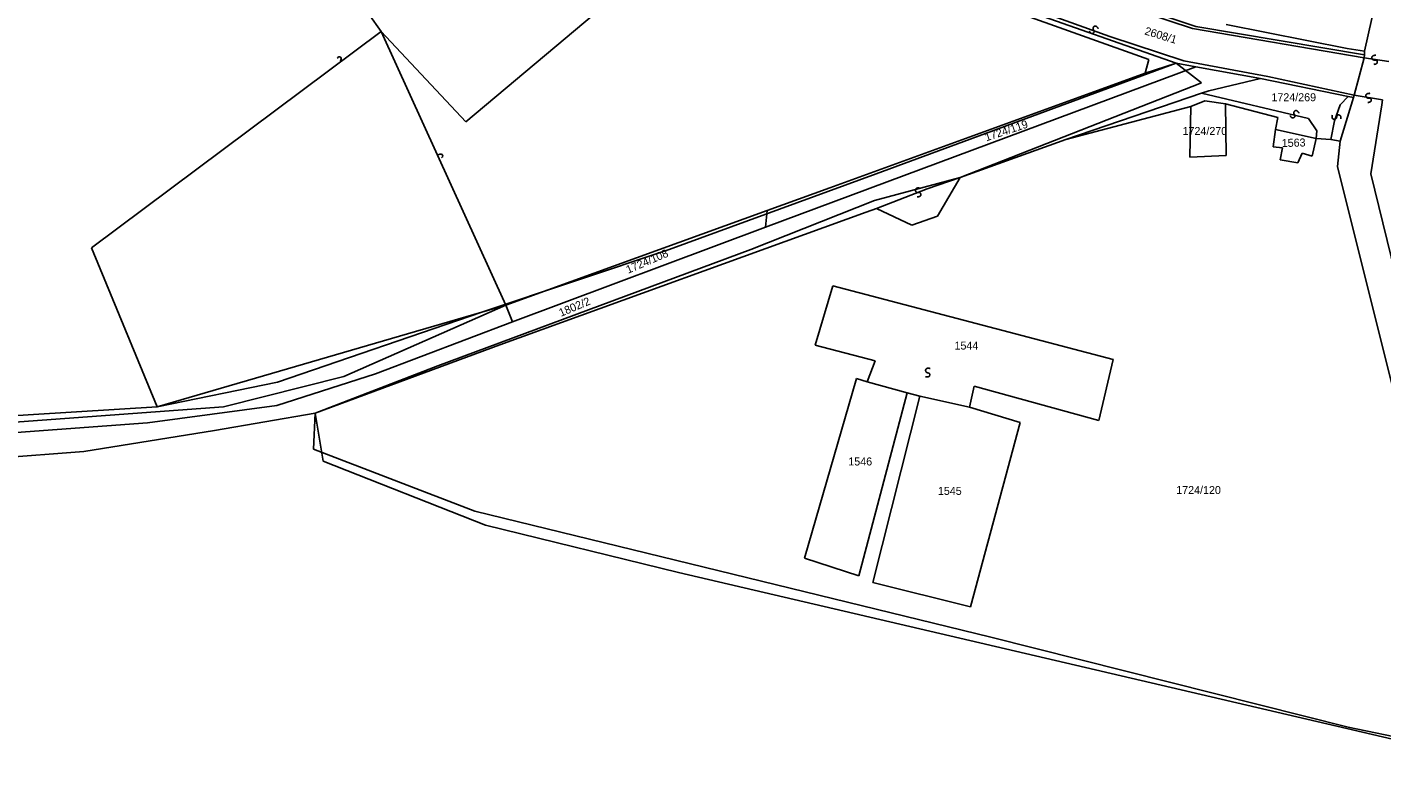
# Model space of a CAD drawing. Extents: x -581999 to -572728, y -1219553 to -1212032.
# Drawn here: x -578955.2 to -578616.8, y -1215563.4 to -1215379.4 of the extents above; entities that cross this region are included whole.
import ezdxf

# ---------------------------------------------------------------- set-up
doc = ezdxf.new("R2010")
doc.units = 0
for name, color, linetype in [('Vrstva 1', 7, 'Continuous'), ('Vrstva 2', 7, 'Continuous'), ('Vrstva 4', 7, 'Continuous'), ('Vrstva 6', 7, 'Continuous'), ('Vrstva 63', 7, 'Continuous')]:
    doc.layers.add(name, color=color, linetype=linetype)

msp = doc.modelspace()

# ---------------------------------------------------------------- linework, layer by layer
at = {"layer": 'Vrstva 1'}
for p, q in [((-578760.509, -1215331.523), (-578845.631, -1215403.127)), ((-578866.81, -1215380.502), (-578873.87, -1215370.57)), ((-578709.273, -1215375.274), (-578674.955, -1215387.516)), ((-578707.581, -1215374.594), (-578668.188, -1215388.422)), ((-578655.655, -1215378.755), (-578625.458, -1215384.809)), ((-578939.172, -1215434.581), (-578866.81, -1215380.502)), ((-578866.81, -1215380.502), (-578835.63, -1215448.928)), ((-578845.631, -1215403.127), (-578866.81, -1215380.502)), ((-578625.458, -1215384.809), (-578621.144, -1215385.458)), ((-578674.955, -1215387.516), (-578675.921, -1215390.916)), ((-578668.188, -1215388.422), (-578663.25, -1215389.334)), ((-578623.694, -1215396.422), (-578621.211, -1215387.123)), ((-578770.802, -1215429.419), (-578663.25, -1215389.334)), ((-578663.25, -1215389.334), (-578647.054, -1215392.279)), ((-578659.977, -1215395.359), (-578647.054, -1215392.279)), ((-578647.054, -1215392.279), (-578625.188, -1215396.746)), ((-578661.834, -1215395.951), (-578659.977, -1215395.359)), ((-578695.692, -1215407.535), (-578661.834, -1215395.951)), ((-578695.692, -1215407.535), (-578664.512, -1215399.258)), ((-578664.714, -1215411.951), (-578664.512, -1215399.258)), ((-578664.512, -1215399.258), (-578660.982, -1215397.879)), ((-578660.982, -1215397.879), (-578655.834, -1215398.568)), ((-578655.834, -1215398.568), (-578642.745, -1215402.017)), ((-578655.834, -1215398.568), (-578655.655, -1215411.519)), ((-578627.154, -1215407.949), (-578623.872, -1215397.051)), ((-578625.188, -1215396.746), (-578623.872, -1215397.051)), ((-578623.872, -1215397.051), (-578623.694, -1215396.422)), ((-578642.745, -1215402.017), (-578643.333, -1215405.052)), ((-578643.333, -1215405.052), (-578643.921, -1215409.329)), ((-578633.185, -1215407.26), (-578643.333, -1215405.052)), ((-578722.166, -1215417.055), (-578695.692, -1215407.535)), ((-578643.921, -1215409.329), (-578641.568, -1215409.605)), ((-578634.214, -1215411.674), (-578633.185, -1215407.26)), ((-578633.185, -1215407.26), (-578629.508, -1215407.535)), ((-578629.508, -1215407.535), (-578627.154, -1215407.949)), ((-578627.154, -1215407.949), (-578627.89, -1215414.295)), ((-578655.655, -1215411.519), (-578664.714, -1215411.951)), ((-578641.568, -1215409.605), (-578642.156, -1215412.64)), ((-578642.156, -1215412.64), (-578637.744, -1215413.33)), ((-578637.744, -1215413.33), (-578636.714, -1215410.984)), ((-578636.714, -1215410.984), (-578634.214, -1215411.674)), ((-578627.89, -1215414.295), (-578613.918, -1215470.029)), ((-578722.166, -1215417.055), (-578727.755, -1215426.711)), ((-578837.154, -1215458.836), (-578745.601, -1215425.733)), ((-578770.342, -1215425.262), (-578770.802, -1215429.419)), ((-578745.601, -1215425.733), (-578743.051, -1215424.78)), ((-578734.226, -1215428.919), (-578743.051, -1215424.78)), ((-578833.94, -1215453.161), (-578770.802, -1215429.419)), ((-578727.755, -1215426.711), (-578734.226, -1215428.919)), ((-578922.744, -1215474.383), (-578939.172, -1215434.581)), ((-578758.347, -1215458.993), (-578753.934, -1215444.094)), ((-578753.934, -1215444.094), (-578683.926, -1215462.579)), ((-578835.63, -1215448.928), (-578922.744, -1215474.383)), ((-578876.103, -1215466.802), (-578835.63, -1215448.928)), ((-578835.63, -1215448.928), (-578833.94, -1215453.161)), ((-578868.184, -1215466.109), (-578833.94, -1215453.161)), ((-578883.275, -1215475.991), (-578837.154, -1215458.836)), ((-578743.345, -1215462.855), (-578758.347, -1215458.993)), ((-578745.404, -1215468.098), (-578743.345, -1215462.855)), ((-578683.926, -1215462.579), (-578687.456, -1215477.754)), ((-578906.14, -1215474.388), (-578876.103, -1215466.802)), ((-578892.829, -1215474.056), (-578868.184, -1215466.109)), ((-578760.994, -1215512.243), (-578748.051, -1215467.27)), ((-578718.636, -1215469.201), (-578719.813, -1215474.443)), ((-578687.456, -1215477.754), (-578718.636, -1215469.201)), ((-578735.403, -1215470.857), (-578747.463, -1215516.657)), ((-578743.933, -1215518.313), (-578732.167, -1215471.684)), ((-578735.403, -1215470.857), (-578732.167, -1215471.684)), ((-578732.167, -1215471.684), (-578719.813, -1215474.443)), ((-578995.304, -1215480.887), (-578906.14, -1215474.388)), ((-578925.177, -1215478.39), (-578892.829, -1215474.056)), ((-578908.465, -1215480.316), (-578883.275, -1215475.991)), ((-578881.302, -1215487.963), (-578883.275, -1215475.991)), ((-578719.813, -1215474.443), (-578707.164, -1215478.306)), ((-578941.085, -1215485.515), (-578908.465, -1215480.316)), ((-578707.164, -1215478.306), (-578719.518, -1215524.383)), ((-578972.918, -1215487.968), (-578941.085, -1215485.515)), ((-578840.709, -1215503.966), (-578881.302, -1215487.963)), ((-578792.468, -1215515.83), (-578840.709, -1215503.966)), ((-578747.463, -1215516.657), (-578760.994, -1215512.243)), ((-578588.764, -1215563.424), (-578792.468, -1215515.83)), ((-578719.518, -1215524.383), (-578743.933, -1215518.313))]:
    msp.add_line(p, q, dxfattribs=at)
for points in [[(-578621.211, -1215387.123), (-578621.148, -1215386.39), (-578621.144, -1215385.458), (-578619.265, -1215377.308), (-578619.278, -1215360.679), (-578627.571, -1215334.027), (-578642.467, -1215288.699)], [(-578727.079, -1215347.249), (-578698.629, -1215367.438), (-578663.267, -1215379.248), (-578621.148, -1215386.39)], [(-578668.188, -1215388.422), (-578675.921, -1215390.916), (-578754.671, -1215419.606)], [(-578612.489, -1215445.07), (-578619.496, -1215416.092), (-578616.755, -1215398.896), (-578616.594, -1215397.628)], [(-578835.63, -1215448.928), (-578770.342, -1215425.262), (-578754.671, -1215419.606)], [(-578748.051, -1215467.27), (-578745.404, -1215468.098), (-578735.403, -1215470.857)], [(-579029.92, -1215486.337), (-578990.69, -1215483.183), (-578925.177, -1215478.39)]]:
    msp.add_lwpolyline(points, dxfattribs=at)
at = {"layer": 'Vrstva 4'}
for p, q in [((-578699.606, -1215368.02), (-578664.052, -1215379.79)), ((-578664.052, -1215379.79), (-578621.211, -1215387.123)), ((-578645.294, -1215391.736), (-578666.267, -1215387.829)), ((-578645.294, -1215391.736), (-578623.694, -1215396.422)), ((-578635.097, -1215402.293), (-578661.834, -1215395.951)), ((-578628.625, -1215402.845), (-578627.154, -1215398.844)), ((-578627.154, -1215398.844), (-578625.188, -1215396.746)), ((-578633.037, -1215405.328), (-578635.097, -1215402.293)), ((-578633.185, -1215407.26), (-578633.037, -1215405.328)), ((-578629.508, -1215407.535), (-578628.625, -1215402.845)), ((-578730.362, -1215419.896), (-578722.166, -1215417.055)), ((-578743.051, -1215424.78), (-578730.362, -1215419.896))]:
    msp.add_line(p, q, dxfattribs=at)
for points in [[(-578756.119, -1215331.928), (-578732.6, -1215355.342), (-578718.137, -1215366.453), (-578706.541, -1215373.919), (-578684.718, -1215381.734), (-578666.267, -1215387.829)], [(-578621.211, -1215387.123), (-578615.047, -1215388.059)], [(-578616.594, -1215397.628), (-578623.694, -1215396.422)]]:
    msp.add_lwpolyline(points, dxfattribs=at)
at = {"layer": 'Vrstva 6'}
for points, degree in [([(-578689.874, -1215380.433), (-578689.394, -1215381.14), (-578688.7, -1215380.829), (-578688.623, -1215380.429), (-578688.859, -1215380.084), (-578688.944, -1215379.752), (-578688.862, -1215379.462), (-578688.718, -1215379.282), (-578688.482, -1215379.154), (-578688.117, -1215379.19), (-578687.69, -1215379.629), (-578687.635, -1215379.802)], 2), ([(-578876.918, -1215387.946), (-578876.567, -1215387.167), (-578877.195, -1215386.739), (-578877.571, -1215386.88), (-578877.685, -1215387.128), (-578877.75, -1215387.229)], 3), ([(-578618.803, -1215388.742), (-578617.952, -1215388.653), (-578617.9, -1215387.895), (-578618.216, -1215387.639), (-578618.632, -1215387.684), (-578618.964, -1215387.602), (-578619.181, -1215387.394), (-578619.272, -1215387.182), (-578619.273, -1215386.913), (-578619.07, -1215386.608), (-578618.482, -1215386.438), (-578618.302, -1215386.471)], 2), ([(-578620.313, -1215398.261), (-578619.462, -1215398.172), (-578619.41, -1215397.414), (-578619.726, -1215397.158), (-578620.142, -1215397.203), (-578620.474, -1215397.121), (-578620.691, -1215396.913), (-578620.782, -1215396.701), (-578620.783, -1215396.432), (-578620.58, -1215396.127), (-578619.992, -1215395.957), (-578619.812, -1215395.99)], 2), ([(-578639.726, -1215401.558), (-578639.246, -1215402.265), (-578638.552, -1215401.954), (-578638.475, -1215401.554), (-578638.711, -1215401.209), (-578638.796, -1215400.877), (-578638.714, -1215400.587), (-578638.57, -1215400.407), (-578638.334, -1215400.279), (-578637.969, -1215400.315), (-578637.542, -1215400.754), (-578637.487, -1215400.927)], 2), ([(-578627.057, -1215402.382), (-578626.962, -1215401.531), (-578627.692, -1215401.319), (-578628.009, -1215401.573), (-578628.054, -1215401.989), (-578628.205, -1215402.296), (-578628.454, -1215402.463), (-578628.681, -1215402.507), (-578628.944, -1215402.451), (-578629.199, -1215402.187), (-578629.239, -1215401.577), (-578629.169, -1215401.408)], 2), ([(-578852.556, -1215411.394), (-578851.826, -1215410.948), (-578851.323, -1215411.518), (-578851.417, -1215411.908), (-578851.649, -1215412.052), (-578851.741, -1215412.129)], 3), ([(-578732.853, -1215421.885), (-578732.002, -1215421.796), (-578731.95, -1215421.038), (-578732.266, -1215420.782), (-578732.682, -1215420.827), (-578733.014, -1215420.745), (-578733.231, -1215420.537), (-578733.322, -1215420.325), (-578733.323, -1215420.056), (-578733.12, -1215419.751), (-578732.532, -1215419.581), (-578732.352, -1215419.614)], 2), ([(-578730.762, -1215466.844), (-578729.921, -1215466.996), (-578729.658, -1215466.282), (-578729.89, -1215465.948), (-578730.302, -1215465.875), (-578730.598, -1215465.703), (-578730.748, -1215465.442), (-578730.776, -1215465.213), (-578730.702, -1215464.955), (-578730.421, -1215464.719), (-578729.809, -1215464.721), (-578729.646, -1215464.803)], 2)]:
    msp.add_open_spline(points, degree=degree, dxfattribs=at)
at = {"layer": 'Vrstva 63'}
for p, q in [((-578743.152, -1215416.136), (-578668.188, -1215388.422)), ((-578668.188, -1215388.422), (-578661.797, -1215393.329)), ((-578661.797, -1215393.329), (-578722.166, -1215417.055)), ((-578794.833, -1215435.011), (-578743.152, -1215416.136)), ((-578722.166, -1215417.055), (-578743.545, -1215422.821)), ((-578743.545, -1215422.821), (-578774.396, -1215435.011)), ((-578774.396, -1215435.011), (-578852.606, -1215464.11)), ((-578841.602, -1215450.74), (-578794.833, -1215435.011)), ((-578892.694, -1215468.239), (-578841.602, -1215450.74)), ((-578852.606, -1215464.11), (-578883.275, -1215475.991)), ((-578922.744, -1215474.383), (-578892.694, -1215468.239)), ((-578996.057, -1215478.856), (-578953.611, -1215476.3)), ((-578953.611, -1215476.3), (-578922.744, -1215474.383)), ((-578883.275, -1215475.991), (-578883.654, -1215484.951)), ((-578883.654, -1215484.951), (-578843.37, -1215500.483)), ((-578843.37, -1215500.483), (-578714.461, -1215531.941)), ((-578714.461, -1215531.941), (-578625.23, -1215554.488)), ((-578625.23, -1215554.488), (-578593.677, -1215561.005))]:
    msp.add_line(p, q, dxfattribs=at)

# ---------------------------------------------------------------- texts
at = {"layer": 'Vrstva 2'}
for s, rotation, p in [('2608/1', 343.13746, (-578676.195, -1215381.225)), ('1724/119', 18.47223, (-578715.592, -1215408.013)), ('1563', 1.58614, (-578641.762, -1215409.418)), ('1724/108', 23.25646, (-578805.091, -1215441.105)), ('1802/2', 22.9417, (-578821.868, -1215451.884))]:
    msp.add_text(s, height=2, rotation=rotation, dxfattribs=at).set_placement(p)
for s, p in [('1724/269', (-578644.367, -1215397.963)), ('1724/270', (-578666.567, -1215406.4)), ('1544', (-578723.544, -1215460.052)), ('1546', (-578750.074, -1215489.041)), ('1545', (-578727.696, -1215496.396)), ('1724/120', (-578668.146, -1215496.181))]:
    msp.add_text(s, height=2, dxfattribs=at).set_placement(p)

doc.saveas('drawing.dxf')
